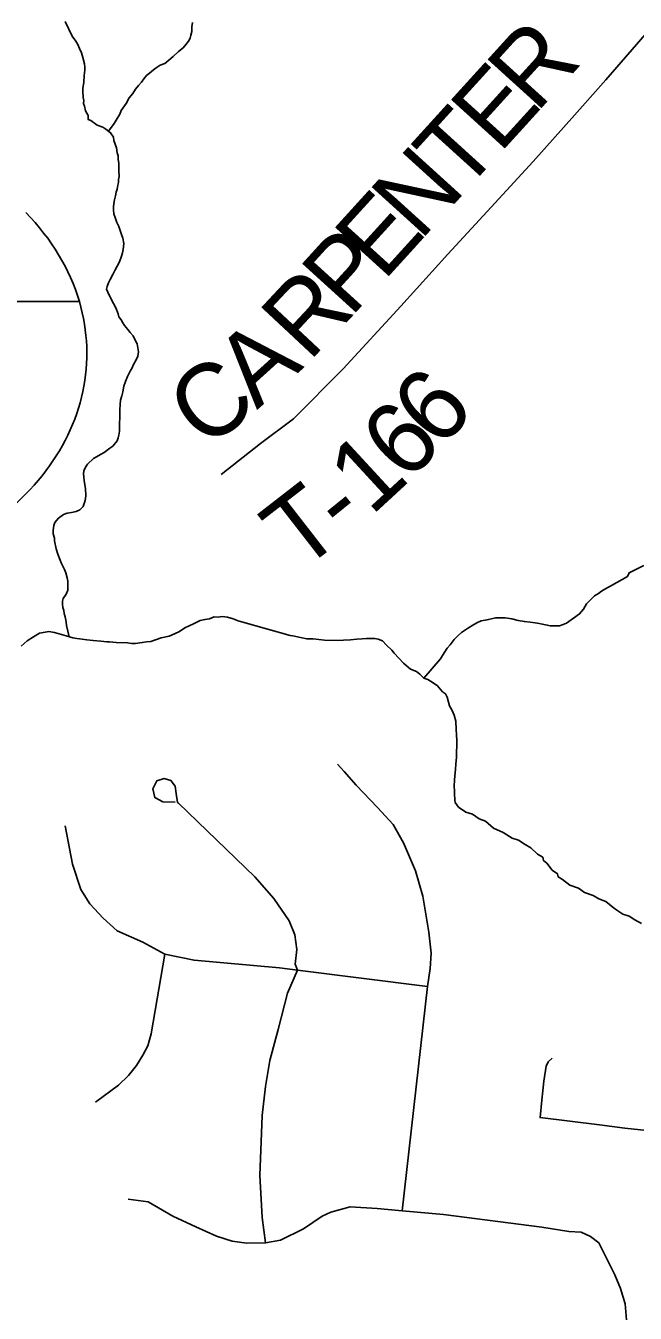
# Model space of a CAD drawing. Extents: x 44.2 to 78.2, y 4.5 to 26.5.
# Drawn here: x 51.062 to 51.539, y 23.779 to 24.786 of the extents above; entities that cross this region are included whole.
import ezdxf

# ---------------------------------------------------------------- set-up
doc = ezdxf.new("R2010")
doc.units = 0
for name, color, linetype in [('GM_X_Interstate_Shield', 7, 'Continuous'), ('GM_X_Minor_River', 7, 'Continuous'), ('GM_X_Township_Road', 7, 'Continuous'), ('GM_X_Township_Road_Text', 7, 'Continuous')]:
    doc.layers.add(name, color=color, linetype=linetype)

msp = doc.modelspace()

# ---------------------------------------------------------------- linework, layer by layer
at = {"layer": 'GM_X_Interstate_Shield'}
msp.add_line((51.1043, 24.5707), (50.7609, 24.5707), dxfattribs=at)
msp.add_line((51.1043, 24.5707), (50.7609, 24.5707), dxfattribs=at)
for start_param, end_param in [(0.230566, 0.669003), (4.913747, 6.513751)]:
    msp.add_ellipse((50.8882, 24.5301), major_axis=(0.2219, 0), ratio=0.8, start_param=start_param, end_param=end_param, dxfattribs=at)
at = {"layer": 'GM_X_Minor_River'}
for points in [[(51.1309, 24.6446), (51.1313, 24.6473), (51.1318, 24.6503), (51.1326, 24.6533), (51.1331, 24.6563), (51.1339, 24.6586), (51.1344, 24.6616), (51.1348, 24.6639), (51.1349, 24.6661), (51.1353, 24.6684), (51.135, 24.673), (51.1352, 24.6787), (51.1345, 24.6821), (51.1346, 24.6847), (51.1339, 24.687), (51.1332, 24.6908), (51.1321, 24.6939), (51.1311, 24.6966), (51.1308, 24.6993), (51.1286, 24.7027), (51.1248, 24.7055), (51.1226, 24.7071), (51.1181, 24.7087), (51.1132, 24.7122), (51.111, 24.7131), (51.1111, 24.7161), (51.1089, 24.7199), (51.1082, 24.7234), (51.1075, 24.7257), (51.1076, 24.7279), (51.1072, 24.7302), (51.107, 24.7352), (51.107, 24.7374), (51.1076, 24.7424), (51.1081, 24.7476), (51.1086, 24.7518), (51.1086, 24.7541), (51.1083, 24.7567), (51.1069, 24.7617), (51.1059, 24.7652), (51.1044, 24.7686), (51.103, 24.7717), (51.1015, 24.7744), (51.0986, 24.7782), (51.0932, 24.7898)], [(51.127, 24.7039), (51.1314, 24.7099), (51.133, 24.7125), (51.1358, 24.7173), (51.137, 24.72), (51.1409, 24.7255), (51.1433, 24.73), (51.1461, 24.7334), (51.1481, 24.7367), (51.1504, 24.7397), (51.1528, 24.7423), (51.1547, 24.7449), (51.1567, 24.7475), (51.159, 24.7493), (51.1621, 24.7519), (51.1644, 24.7534), (51.1675, 24.7556), (51.171, 24.757), (51.1741, 24.7596), (51.1776, 24.7625), (51.1818, 24.7662), (51.1853, 24.7691), (51.1877, 24.7721), (51.1896, 24.7743), (51.1908, 24.7766), (51.1913, 24.7792), (51.1921, 24.7819), (51.1922, 24.7857), (51.1927, 24.7891)], [(51.0963, 24.3083), (51.0941, 24.3171), (51.0938, 24.3201), (51.0931, 24.3239), (51.0924, 24.3266), (51.0921, 24.3289), (51.0914, 24.3312), (51.0911, 24.3338), (51.0911, 24.3361), (51.0916, 24.3384), (51.0939, 24.3417), (51.0952, 24.3447), (51.0953, 24.3519), (51.0947, 24.3546), (51.0936, 24.3584), (51.0925, 24.3611), (51.09, 24.3661), (51.0893, 24.3684), (51.0875, 24.373), (51.0861, 24.3772), (51.0848, 24.3833), (51.0848, 24.3856), (51.0838, 24.389), (51.0838, 24.3917), (51.0843, 24.3955), (51.0851, 24.3977), (51.0879, 24.4011), (51.0917, 24.404), (51.0948, 24.4051), (51.0982, 24.4057), (51.1017, 24.4064), (51.1047, 24.4078), (51.1071, 24.4104), (51.1087, 24.4149), (51.1092, 24.4187), (51.109, 24.4244), (51.108, 24.4305), (51.1077, 24.4336), (51.1074, 24.4358), (51.1078, 24.4381), (51.109, 24.4411), (51.1106, 24.4433), (51.1153, 24.4478), (51.1176, 24.4492), (51.1207, 24.451), (51.1237, 24.4525), (51.128, 24.4558), (51.1303, 24.4576), (51.1338, 24.4617), (51.1347, 24.4639), (51.1351, 24.4662), (51.1356, 24.4692), (51.136, 24.4859), (51.1361, 24.4901), (51.1365, 24.4935), (51.1374, 24.4969), (51.1382, 24.4999), (51.1391, 24.5044), (51.1403, 24.5082), (51.142, 24.5119), (51.144, 24.5161), (51.1455, 24.5187), (51.1464, 24.5209), (51.1487, 24.525), (51.15, 24.528), (51.1504, 24.5314), (51.1494, 24.5375), (51.1476, 24.541), (51.1462, 24.5437), (51.144, 24.5464), (51.1421, 24.5487), (51.1395, 24.5518), (51.1381, 24.5541), (51.137, 24.5564), (51.1352, 24.5588), (51.1345, 24.5611), (51.1327, 24.5657), (51.1309, 24.5691), (51.1276, 24.5757), (51.1255, 24.5803), (51.1259, 24.5825), (51.1271, 24.5852), (51.1283, 24.5878), (51.1303, 24.5919), (51.1319, 24.5949), (51.1339, 24.5983), (51.1355, 24.6016), (51.1371, 24.6061), (51.138, 24.6088), (51.1384, 24.6114), (51.1388, 24.6137), (51.1389, 24.616), (51.1382, 24.6202), (51.1375, 24.6224), (51.1365, 24.6255), (51.1351, 24.6293), (51.1336, 24.6324), (51.1326, 24.6355), (51.1311, 24.6393), (51.1308, 24.6423), (51.1309, 24.6446)], [(51.3737, 24.276), (51.3866, 24.2912), (51.3882, 24.2938), (51.3918, 24.2994), (51.3941, 24.302), (51.3973, 24.3061), (51.4004, 24.3094), (51.4031, 24.3116), (51.4085, 24.3153), (51.412, 24.3175), (51.4151, 24.3193), (51.4185, 24.3207), (51.4231, 24.3217), (51.4296, 24.3231), (51.4349, 24.3233), (51.4372, 24.3233), (51.4425, 24.3224), (51.4474, 24.3211), (51.4523, 24.3202), (51.4569, 24.3197), (51.4607, 24.3192), (51.4637, 24.3188), (51.4663, 24.3183), (51.4701, 24.3175), (51.4724, 24.317), (51.4796, 24.3168), (51.4827, 24.3179), (51.4853, 24.319), (51.4908, 24.323), (51.4954, 24.3263), (51.4985, 24.33), (51.5009, 24.3341), (51.5044, 24.3378), (51.5072, 24.3404), (51.5102, 24.3422), (51.5126, 24.344), (51.5153, 24.3455), (51.5203, 24.3484), (51.533, 24.3556), (51.5342, 24.3583), (51.5457, 24.364)], [(51.0587, 24.3009), (51.0634, 24.3053), (51.0684, 24.3083), (51.073, 24.3112), (51.0761, 24.3118), (51.0803, 24.3125), (51.0848, 24.3116), (51.0939, 24.3091), (51.0965, 24.3083), (51.0992, 24.3074), (51.1022, 24.307), (51.1063, 24.3065), (51.1101, 24.306), (51.1151, 24.3055), (51.1211, 24.305), (51.1257, 24.3045), (51.1279, 24.3044), (51.1329, 24.3039), (51.142, 24.3037), (51.145, 24.3032), (51.148, 24.3031), (51.1534, 24.3038), (51.1568, 24.3044), (51.1602, 24.3047), (51.1683, 24.3075), (51.1744, 24.3089), (51.1786, 24.3107), (51.1825, 24.3125), (51.1867, 24.3154), (51.1936, 24.3186), (51.1986, 24.3212), (51.2024, 24.3218), (51.2059, 24.3225), (51.2097, 24.3239), (51.2128, 24.3238), (51.2158, 24.3241), (51.22, 24.3236), (51.2245, 24.3224), (51.2283, 24.3208), (51.232, 24.3199), (51.2692, 24.3094)], [(51.2692, 24.3094), (51.2713, 24.309), (51.2773, 24.3077), (51.2822, 24.3068), (51.2871, 24.3067), (51.2959, 24.3057), (51.3061, 24.3054), (51.3107, 24.3057), (51.3164, 24.3059), (51.3213, 24.3066), (51.3255, 24.3068), (51.3289, 24.3071), (51.3324, 24.307), (51.3354, 24.307), (51.338, 24.3065)], [(51.338, 24.3065), (51.3414, 24.3053), (51.3444, 24.3018), (51.3485, 24.2979), (51.3503, 24.2956), (51.3577, 24.2878), (51.3633, 24.2831), (51.3678, 24.2811), (51.3704, 24.2791), (51.3737, 24.276), (51.3767, 24.2748), (51.3808, 24.2724), (51.3842, 24.27), (51.3883, 24.2654), (51.3905, 24.2638), (51.392, 24.2611), (51.3937, 24.2542), (51.3959, 24.2507), (51.3973, 24.2469), (51.3987, 24.2423), (51.3989, 24.2359), (51.3992, 24.2317), (51.3994, 24.2271), (51.3991, 24.2142), (51.3986, 24.2086), (51.3985, 24.2044), (51.3981, 24.2021), (51.3975, 24.1965), (51.3974, 24.1911), (51.3977, 24.1881), (51.3976, 24.1855), (51.3979, 24.1809), (51.3982, 24.1786), (51.4008, 24.1751), (51.4064, 24.1712), (51.4117, 24.1695), (51.4169, 24.166), (51.4218, 24.164), (51.4281, 24.1585), (51.4356, 24.1552), (51.4427, 24.1509), (51.4476, 24.1492), (51.4528, 24.1457), (51.4573, 24.1433), (51.4625, 24.1382), (51.4666, 24.1358), (51.4673, 24.1332), (51.4699, 24.1312), (51.474, 24.1258), (51.4781, 24.123), (51.4788, 24.1204), (51.4821, 24.1184), (51.4877, 24.1141), (51.4945, 24.1116), (51.4994, 24.1084), (51.5061, 24.106), (51.5106, 24.1032), (51.5159, 24.1012), (51.5218, 24.0965), (51.5245, 24.0945), (51.5293, 24.0913), (51.5342, 24.0897), (51.5387, 24.0869), (51.5439, 24.0841)]]:
    msp.add_lwpolyline(points, dxfattribs=at)
at = {"layer": 'GM_X_Township_Road'}
for points in [[(51.4956, 24.7211), (51.516, 24.7441), (51.5519, 24.7855), (51.5562, 24.7888)], [(51.2152, 24.4352), (51.246, 24.4596), (51.2716, 24.4789), (51.3105, 24.5179), (51.3557, 24.567), (51.3924, 24.6076), (51.4262, 24.6445), (51.4592, 24.6802), (51.4914, 24.7164), (51.4956, 24.7211)], [(51.3567, 23.8591), (51.3764, 24.0346), (51.3785, 24.0487), (51.3793, 24.0608), (51.3776, 24.0772), (51.3729, 24.1055), (51.3671, 24.1251), (51.3576, 24.1471), (51.3496, 24.1614), (51.3373, 24.1748), (51.3206, 24.1922), (51.3113, 24.203), (51.3062, 24.2087)], [(51.1818, 24.1782), (51.1811, 24.1788), (51.1799, 24.1856), (51.1792, 24.1915), (51.1758, 24.196), (51.1706, 24.1974), (51.1647, 24.1956), (51.1617, 24.1893), (51.1632, 24.1826), (51.1695, 24.1792), (51.1792, 24.1789)], [(51.2498, 23.8341), (51.2473, 23.8539), (51.2454, 23.887), (51.2463, 23.9132), (51.2471, 23.9337), (51.2497, 23.9564), (51.2531, 23.9769), (51.2596, 24.001), (51.2671, 24.0296), (51.2749, 24.0475), (51.2731, 24.0522), (51.2743, 24.0636), (51.2728, 24.0751), (51.2682, 24.0862), (51.2563, 24.1037), (51.2414, 24.1206), (51.1818, 24.1782)], [(51.3764, 24.0346), (51.2749, 24.0475), (51.2608, 24.0493), (51.194, 24.0553), (51.171, 24.0601), (51.1539, 24.0695), (51.1337, 24.0782), (51.1228, 24.0881), (51.1125, 24.0993), (51.1055, 24.1106), (51.0989, 24.1304), (51.0931, 24.1605)], [(51.1169, 23.9442), (51.1348, 23.9576), (51.1427, 23.965), (51.149, 23.9728), (51.1538, 23.981), (51.1579, 23.9884), (51.1605, 23.9978), (51.171, 24.0601)], [(51.4739, 23.9786), (51.4709, 23.9758), (51.4693, 23.9725), (51.4676, 23.9606), (51.4659, 23.9457), (51.4645, 23.9321), (51.511, 23.9266), (51.5309, 23.9239), (51.553, 23.9214)], [(51.5321, 23.7739), (51.5311, 23.7864), (51.5274, 23.7985), (51.523, 23.809), (51.5179, 23.8195), (51.5106, 23.8342), (51.504, 23.839), (51.4967, 23.8424), (51.4871, 23.8431), (51.466, 23.8465), (51.3889, 23.8563), (51.3567, 23.8591), (51.3371, 23.861), (51.316, 23.8623), (51.301, 23.8581), (51.294, 23.855), (51.2794, 23.8452), (51.2615, 23.8363), (51.2498, 23.8341), (51.2351, 23.8338), (51.2238, 23.8354), (51.2116, 23.8393), (51.1954, 23.8466), (51.1773, 23.8551), (51.1581, 23.8662), (51.1424, 23.8684)]]:
    msp.add_lwpolyline(points, dxfattribs=at)

# ---------------------------------------------------------------- texts
at = {"layer": 'GM_X_Township_Road_Text'}
for s, rotation, p in [('R', 47.7692, (51.4614, 24.7173)), ('E', 47.7678, (51.4328, 24.6858)), ('T', 47.7678, (51.4043, 24.6544)), ('N', 47.7675, (51.3707, 24.6174)), ('E', 47.7735, (51.3421, 24.5859)), ('P', 47.7302, (51.3163, 24.5575)), ('R', 46.9383, (51.2838, 24.5228)), ('A', 42.1832, (51.2431, 24.4856)), ('C', 37.9003, (51.2027, 24.4539)), ('6', 46.9399, (51.3859, 24.4543)), ('6', 45.6517, (51.3605, 24.4283)), ('1', 42.6515, (51.3324, 24.4023)), ('T', 37.8145, (51.2767, 24.3582)), ('-', 39.0019, (51.3113, 24.385))]:
    msp.add_text(s, height=0.0568, rotation=rotation, dxfattribs=at).set_placement(p)

doc.saveas('drawing.dxf')
